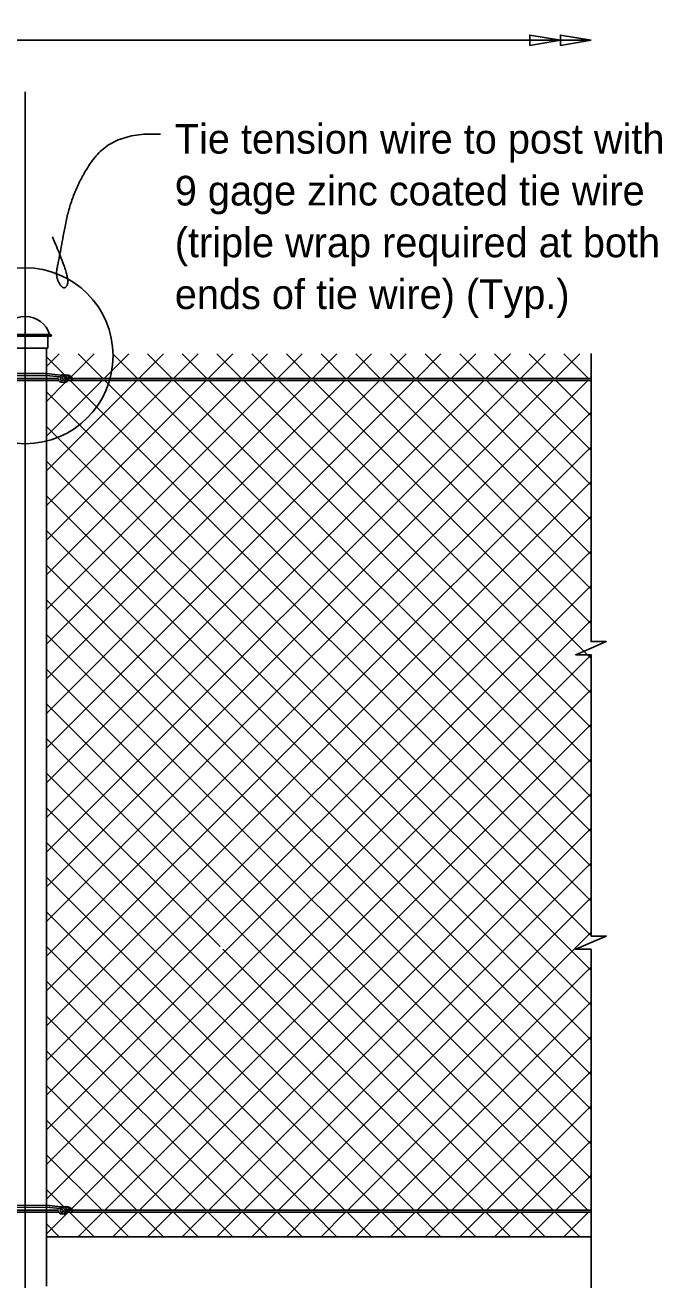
# Model space of a CAD drawing. Extents: x 0.2 to 40.8, y 0.5 to 25.7.
# Drawn here: x 24.62 to 28.94, y 16.93 to 25.46 of the extents above; entities that cross this region are included whole.
import ezdxf

# ---------------------------------------------------------------- set-up
doc = ezdxf.new("R2010")
doc.units = 0
for name, color, linetype in [('CL_Major', 7, 'Continuous'), ('Dimension', 7, 'Continuous'), ('Miscellaneous', 7, 'Continuous'), ('SteelMisc', 7, 'Continuous'), ('SteelMisc_h', 7, 'Continuous'), ('SupstrConc', 7, 'Continuous')]:
    doc.layers.add(name, color=color, linetype=linetype)

msp = doc.modelspace()

# ---------------------------------------------------------------- linework, layer by layer
at = {"layer": 'CL_Major'}
msp.add_line((24.6151, 11.3358), (24.6151, 25.0052), dxfattribs=at)
at = {"layer": 'Dimension'}
for points in [[(13.615, 25.3556), (15.0787, 25.3556), (15.0787, 25.4589), (15.1237, 25.3556), (15.1687, 25.2523), (15.1687, 25.3556), (28.4596, 25.3556)], [(28.4596, 23.2265), (28.4596, 21.2702), (28.5629, 21.2702), (28.4596, 21.2252), (28.3562, 21.1802), (28.4596, 21.1802), (28.4596, 20.2867)], [(28.4596, 20.2867), (28.4596, 19.2689), (28.5629, 19.2689), (28.4596, 19.2239), (28.3562, 19.1789), (28.4596, 19.1789), (28.4596, 16.9746)], [(28.4596, 17.2246), (28.4596, 15.3737), (28.5629, 15.3737), (28.4596, 15.3287), (28.3562, 15.2837), (28.4596, 15.2837), (28.4596, 13.4788)]]:
    msp.add_lwpolyline(points, dxfattribs=at)
for points in [[(28.2513, 25.3556), (28.0431, 25.3909), (28.0431, 25.3203)], [(28.4596, 25.3556), (28.2513, 25.3909), (28.2513, 25.3203)]]:
    msp.add_lwpolyline(points, close=True, dxfattribs=at)
msp.add_circle((24.615, 23.212), 0.5976, dxfattribs=at)
msp.add_open_spline([(25.5348, 24.717), (25.216, 24.7369), (24.9346, 24.348), (24.8419, 23.852), (24.8201, 23.7498), (24.8799, 23.6501), (24.9246, 23.7397), (24.8002, 24.019)], degree=2, dxfattribs=at)
at = {"layer": 'Miscellaneous'}
for p, q in [((24.7609, 23.1379), (24.8475, 23.2245)), ((24.7609, 23.2036), (24.8832, 23.0814)), ((24.928, 23.0694), (25.0832, 23.2245)), ((24.9757, 23.2245), (25.1424, 23.0578)), ((25.1522, 23.0578), (25.3189, 23.2245)), ((25.2114, 23.2245), (25.3781, 23.0578)), ((25.3879, 23.0578), (25.5546, 23.2245)), ((25.4471, 23.2245), (25.6138, 23.0578)), ((25.6236, 23.0578), (25.7903, 23.2245)), ((25.6828, 23.2245), (25.8495, 23.0578)), ((25.8593, 23.0578), (26.026, 23.2245)), ((25.9185, 23.2245), (26.0852, 23.0578)), ((26.095, 23.0578), (26.2617, 23.2245)), ((26.1542, 23.2245), (26.3209, 23.0578)), ((26.3307, 23.0578), (26.4974, 23.2245)), ((26.3899, 23.2245), (26.5566, 23.0578)), ((26.5664, 23.0578), (26.7331, 23.2245)), ((26.6257, 23.2245), (26.7923, 23.0578)), ((26.8021, 23.0578), (26.9688, 23.2245)), ((26.8614, 23.2245), (27.028, 23.0578)), ((27.0378, 23.0578), (27.2045, 23.2245)), ((27.0971, 23.2245), (27.2637, 23.0578)), ((27.2735, 23.0578), (27.4402, 23.2245)), ((27.3328, 23.2245), (27.4994, 23.0578)), ((27.5092, 23.0578), (27.6759, 23.2245)), ((27.5685, 23.2245), (27.7351, 23.0578)), ((27.7449, 23.0578), (27.9116, 23.2245)), ((27.8042, 23.2245), (27.9708, 23.0578)), ((27.9806, 23.0578), (28.1473, 23.2245)), ((28.0399, 23.2245), (28.2065, 23.0578)), ((28.2163, 23.0578), (28.383, 23.2245)), ((28.2756, 23.2245), (28.4422, 23.0578)), ((24.7609, 20.0738), (27.7302, 23.0431)), ((24.7609, 20.5452), (27.2588, 23.0431)), ((24.7609, 21.0166), (26.7874, 23.0431)), ((24.7609, 21.488), (26.316, 23.0431)), ((24.7609, 19.6024), (28.2016, 23.0431)), ((24.7609, 21.7237), (26.0803, 23.0431)), ((24.7609, 21.2523), (26.5517, 23.0431)), ((24.7609, 20.7809), (27.0231, 23.0431)), ((24.7609, 20.3095), (27.4945, 23.0431)), ((24.7609, 19.8381), (27.9659, 23.0431)), ((24.7609, 19.3667), (28.4373, 23.0431)), ((24.7609, 21.9594), (25.8446, 23.0431)), ((24.7609, 22.4308), (25.3732, 23.0431)), ((24.7609, 22.6665), (25.1375, 23.0431)), ((24.7609, 22.9022), (24.8904, 23.0317)), ((24.7653, 22.1995), (25.6089, 23.0431)), ((24.9165, 23.0578), (24.921, 23.0623)), ((24.9214, 23.0431), (28.4595, 19.505)), ((25.1572, 23.0431), (28.4595, 19.7407)), ((25.3929, 23.0431), (28.4595, 19.9764)), ((25.6286, 23.0431), (28.4595, 20.2121)), ((25.8643, 23.0431), (28.4595, 20.4478)), ((26.1, 23.0431), (28.4595, 20.6835)), ((26.3357, 23.0431), (28.4595, 20.9192)), ((26.5714, 23.0431), (28.4595, 21.1549)), ((26.8071, 23.0431), (28.4595, 21.3906)), ((27.0428, 23.0431), (28.4595, 21.6263)), ((27.2785, 23.0431), (28.4595, 21.862)), ((27.5142, 23.0431), (28.4595, 22.0977)), ((27.7499, 23.0431), (28.4595, 22.3334)), ((27.9856, 23.0431), (28.4595, 22.5691)), ((28.2213, 23.0431), (28.4595, 22.8048)), ((24.7609, 22.9679), (28.4595, 19.2693)), ((24.7609, 19.131), (28.4595, 22.8296)), ((24.7609, 22.7322), (28.4595, 19.0336)), ((24.7609, 18.8953), (28.4595, 22.5939)), ((24.7609, 22.4965), (28.4595, 18.7979)), ((24.7609, 18.6596), (28.4595, 22.3582)), ((24.7609, 22.2608), (28.4595, 18.5622)), ((24.7609, 18.4239), (28.4595, 22.1225)), ((24.7609, 22.0251), (28.4595, 18.3265)), ((24.7609, 18.1882), (28.4595, 21.8868)), ((24.7609, 21.7894), (28.4595, 18.0908)), ((24.7609, 17.9525), (28.4595, 21.6511)), ((24.7609, 21.5537), (28.4595, 17.8551)), ((24.7609, 17.7168), (28.4595, 21.4154)), ((24.7609, 21.318), (28.4595, 17.6194)), ((24.7609, 17.4811), (28.4595, 21.1797)), ((24.7609, 21.0823), (28.4373, 17.4059)), ((24.9303, 17.4148), (28.4595, 20.944)), ((24.7609, 20.8466), (28.2016, 17.4059)), ((25.1572, 17.4059), (28.4595, 20.7083)), ((24.7609, 20.6109), (27.9659, 17.4059)), ((25.3929, 17.4059), (28.4595, 20.4726)), ((24.7609, 20.3752), (25.9395, 19.1966)), ((25.6286, 17.4059), (28.4595, 20.2369)), ((24.7609, 20.1395), (27.4945, 17.4059)), ((25.8643, 17.4059), (28.4595, 20.0012)), ((24.7609, 19.9038), (27.2588, 17.4059)), ((26.1, 17.4059), (28.4595, 19.7655)), ((24.7609, 19.6681), (27.0231, 17.4059)), ((26.3357, 17.4059), (28.4595, 19.5298)), ((24.7609, 19.4324), (26.7874, 17.4059)), ((26.5714, 17.4059), (28.4595, 19.2941)), ((24.7609, 19.1967), (26.5517, 17.4059)), ((25.9572, 19.1789), (27.7302, 17.4059)), ((26.8071, 17.4059), (28.4595, 19.0584)), ((24.7609, 18.961), (26.316, 17.4059)), ((27.0428, 17.4059), (28.4595, 18.8227)), ((24.7609, 18.7253), (26.0803, 17.4059)), ((27.2785, 17.4059), (28.4595, 18.587)), ((24.7609, 18.4896), (25.8446, 17.4059)), ((27.5142, 17.4059), (28.4595, 18.3513)), ((24.7609, 18.2539), (25.6089, 17.4059)), ((27.7499, 17.4059), (28.4595, 18.1156)), ((24.7609, 18.0182), (25.3732, 17.4059)), ((27.9856, 17.4059), (28.4595, 17.8799)), ((24.7609, 17.7825), (25.1375, 17.4059)), ((28.2213, 17.4059), (28.4595, 17.6442)), ((24.7609, 17.5468), (24.8783, 17.4294)), ((24.7609, 17.2454), (24.8992, 17.3837)), ((24.9165, 17.3912), (25.0832, 17.2245)), ((24.9757, 17.2245), (25.1424, 17.3912)), ((25.1522, 17.3912), (25.3189, 17.2245)), ((25.2114, 17.2245), (25.3781, 17.3912)), ((25.3879, 17.3912), (25.5546, 17.2245)), ((25.4471, 17.2245), (25.6138, 17.3912)), ((25.6236, 17.3912), (25.7903, 17.2245)), ((25.6828, 17.2245), (25.8495, 17.3912)), ((25.8593, 17.3912), (26.026, 17.2245)), ((25.9185, 17.2245), (26.0852, 17.3912)), ((26.095, 17.3912), (26.2617, 17.2245)), ((26.1542, 17.2245), (26.3209, 17.3912)), ((26.3307, 17.3912), (26.4974, 17.2245)), ((26.3899, 17.2245), (26.5566, 17.3912)), ((26.5664, 17.3912), (26.7331, 17.2245)), ((26.6257, 17.2245), (26.7923, 17.3912)), ((26.8021, 17.3912), (26.9688, 17.2245)), ((26.8614, 17.2245), (27.028, 17.3912)), ((27.0378, 17.3912), (27.2045, 17.2245)), ((27.0971, 17.2245), (27.2637, 17.3912)), ((27.2735, 17.3912), (27.4402, 17.2245)), ((27.3328, 17.2245), (27.4994, 17.3912)), ((27.5092, 17.3912), (27.6759, 17.2245)), ((27.5685, 17.2245), (27.7351, 17.3912)), ((27.7449, 17.3912), (27.9116, 17.2245)), ((27.8042, 17.2245), (27.9708, 17.3912)), ((27.9806, 17.3912), (28.1473, 17.2245)), ((28.0399, 17.2245), (28.2065, 17.3912)), ((28.2163, 17.3912), (28.383, 17.2245)), ((28.2756, 17.2245), (28.4422, 17.3912)), ((24.7641, 17.3078), (24.8475, 17.2245))]:
    msp.add_line(p, q, dxfattribs=at)
at = {"layer": 'SteelMisc'}
for p, q in [((24.4427, 23.3564), (24.7873, 23.3564)), ((24.7873, 23.3442), (24.4427, 23.3442)), ((24.7691, 23.2645), (24.7691, 23.3442)), ((24.7691, 23.2645), (24.461, 23.2645)), ((24.7609, 16.8894), (24.7609, 23.2644)), ((24.4692, 23.0904), (24.7604, 23.0921)), ((24.4692, 23.0759), (24.7604, 23.0776)), ((24.7604, 23.0921), (24.8547, 23.081)), ((24.7604, 23.0776), (24.8525, 23.0682)), ((24.7609, 23.0578), (24.8413, 23.0578)), ((24.7609, 23.0431), (24.8439, 23.0431)), ((24.9067, 23.0431), (28.4595, 23.0431)), ((24.9116, 23.0578), (24.9269, 23.0578)), ((24.9353, 23.0578), (28.4595, 23.0578)), ((24.4692, 17.4385), (24.7604, 17.4402)), ((24.4692, 17.424), (24.7604, 17.4257)), ((24.7604, 17.4402), (24.8547, 17.4291)), ((24.7604, 17.4257), (24.8525, 17.4163)), ((24.7609, 17.4059), (24.8413, 17.4059)), ((24.9116, 17.4059), (24.9269, 17.4059)), ((24.9353, 17.4059), (28.4595, 17.4059)), ((24.7609, 17.3912), (24.8439, 17.3912)), ((24.9059, 17.3912), (28.4595, 17.3912))]:
    msp.add_line(p, q, dxfattribs=at)
msp.add_arc((24.7872, 23.3502), 0.00613, 271.1647, 88.8353, dxfattribs=at)
for centre, major_axis, ratio, start_param, end_param in [((24.6157, 23.3154), (0.1711, 0), 0.957868, 0.252602, 2.888574), ((24.8661, 23.0543), (-0.0251, 0), 0.957868, 0.055352, 0.751829), ((24.8661, 23.0543), (-0.0251, 0), 0.957868, 5.673972, 5.875498), ((24.8732, 23.0664), (-0.0391, 0), 0.957868, 0.863445, 1.200597), ((24.8556, 23.0562), (0.0303, -0.0108), 0.724765, 6.241815, 8.212701), ((24.8506, 23.0433), (0.0259, 0), 0.957868, 0.655696, 1.505671), ((24.8663, 23.0556), (-0.0119, 0), 0.957868, 5.149694, 6.840495), ((24.8663, 23.0556), (-0.0119, 0), 0.957868, 0.560069, 0.643501), ((24.8646, 23.0498), (0.00795, 0), 0.957868, 3.252108, 6.425997), ((24.8658, 23.0476), (-0.0206, -0.0021), 0.798607, 1.063032, 2.950031), ((24.8691, 23.0544), (-0.0295, 0), 0.957868, 2.243629, 5.062245), ((24.859, 23.0521), (0.0139, 0), 0.957868, 5.660958, 7.342751), ((24.8792, 23.0476), (-0.0206, -0.0021), 0.798607, 1.063032, 1.956656), ((24.8879, 23.0598), (-0.023, 0), 0.957868, 3.312645, 4.992926), ((24.8853, 23.0533), (-0.0231, 0), 0.957868, 1.403365, 2.503632), ((24.9004, 23.0453), (-0.0373, 0), 0.957868, 3.175144, 4.79635), ((24.8867, 23.0573), (0.0249, 0), 0.957868, 5.476514, 6.557353), ((24.8792, 23.0056), (0.0724, 0), 0.957868, 0.631079, 1.121037), ((24.8661, 17.4024), (-0.0251, 0), 0.957868, 0.055352, 0.751829), ((24.8661, 17.4024), (-0.0251, 0), 0.957868, 5.673972, 5.875498), ((24.8556, 17.4043), (0.0303, -0.0108), 0.724765, 6.241815, 8.212701), ((24.8506, 17.3914), (0.0259, 0), 0.957868, 0.655696, 1.505671), ((24.8663, 17.4036), (-0.0119, 0), 0.957868, 5.149694, 6.840495), ((24.8663, 17.4036), (-0.0119, 0), 0.957868, 0.560069, 0.643501), ((24.8646, 17.3979), (0.00795, 0), 0.957868, 3.252108, 6.425997), ((24.8691, 17.4025), (-0.0295, 0), 0.957868, 2.243629, 5.062245), ((24.859, 17.4002), (0.0139, 0), 0.957868, 5.660958, 7.342751), ((24.8879, 17.4079), (-0.023, 0), 0.957868, 3.312645, 4.992926), ((24.9004, 17.3934), (-0.0373, 0), 0.957868, 3.175144, 4.79635), ((24.8867, 17.4054), (0.0249, 0), 0.957868, 5.476514, 6.557353), ((24.8792, 17.3537), (0.0724, 0), 0.957868, 0.631079, 1.121037), ((24.8732, 17.4144), (-0.0391, 0), 0.957868, 0.863445, 1.200597), ((24.8658, 17.3957), (-0.0206, -0.0021), 0.798607, 1.063032, 2.950031), ((24.8792, 17.3957), (-0.0206, -0.0021), 0.798607, 1.063032, 1.956656), ((24.8853, 17.4014), (-0.0231, 0), 0.957868, 1.403365, 2.503632)]:
    msp.add_ellipse(centre, major_axis=major_axis, ratio=ratio, start_param=start_param, end_param=end_param, dxfattribs=at)
at = {"layer": 'SteelMisc_h'}
for p, q in [((24.4692, 23.0578), (24.7609, 23.0578)), ((24.4692, 23.0431), (24.7609, 23.0431)), ((24.4692, 17.4059), (24.7609, 17.4059)), ((24.4692, 17.3912), (24.7609, 17.3912))]:
    msp.add_line(p, q, dxfattribs=at)
at = {"layer": 'SupstrConc'}
for q in [(28.4595, 17.2245), (26.002, 17.2245)]:
    msp.add_line((24.7609, 17.2245), q, dxfattribs=at)

# ---------------------------------------------------------------- texts
at = {"layer": 'Dimension'}
for s, p in [('Tie tension wire to post with ', (25.632, 24.5853)), ('9 gage zinc coated tie wire ', (25.632, 24.2333)), ('(triple wrap required at both ', (25.632, 23.8813)), ('ends of tie wire) (Typ.)', (25.632, 23.5293))]:
    msp.add_text(s, height=0.2016, dxfattribs=at).set_placement(p)

doc.saveas('drawing.dxf')
